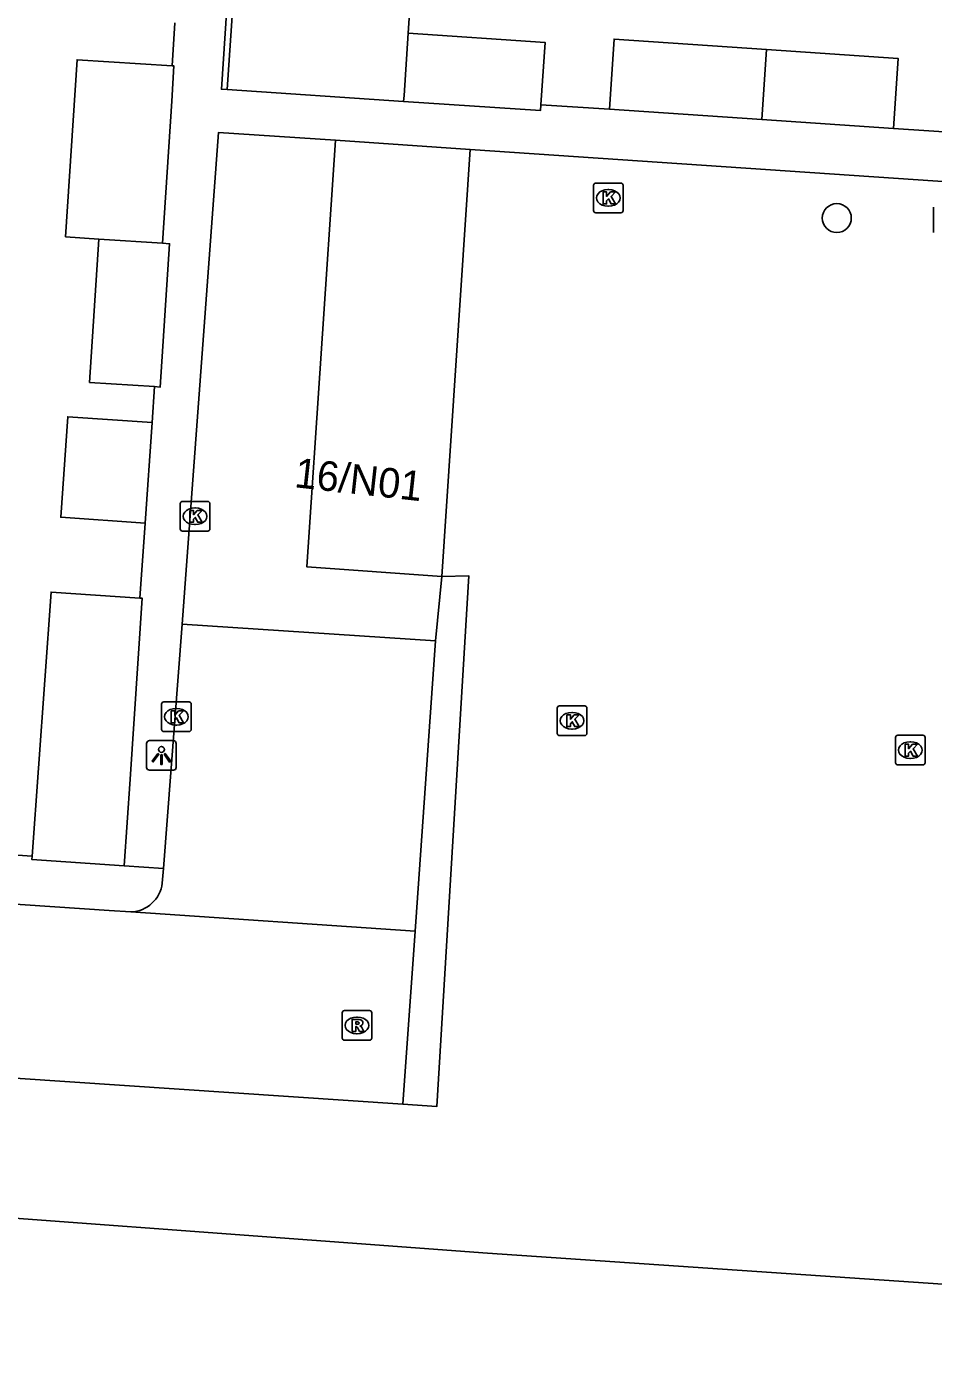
# Model space of a CAD drawing. Extents: x 161848 to 162726, y 385382 to 386521.
# Drawn here: x 162042.65 to 162073.24, y 385672.52 to 385717.48 of the extents above; entities that cross this region are included whole.
import ezdxf

# ---------------------------------------------------------------- set-up
doc = ezdxf.new("R2010")
doc.units = 0
for name, color, linetype in [('IMGEO_Boom', 7, 'Continuous'), ('IMGEO_Hek', 7, 'Continuous'), ('IMGEO_Kolk', 7, 'Continuous'), ('IMGEO_Lichtpunt', 7, 'Continuous'), ('IMGEO_Muur', 7, 'Continuous'), ('IMGEO_Pand', 7, 'Continuous'), ('IMGEO_Pand_nummerreeks', 7, 'Continuous'), ('IMGEO_Rijbaan_lokaal_open', 7, 'Continuous'), ('IMGEO_Rioolput', 7, 'Continuous'), ('IMGEO_Terreindeel_open', 7, 'Continuous'), ('IMGEO_Voetpad_open', 7, 'Continuous')]:
    doc.layers.add(name, color=color, linetype=linetype)

msp = doc.modelspace()

# ---------------------------------------------------------------- linework, layer by layer
at = {"layer": 'IMGEO_Boom'}
msp.add_circle((162069.987, 385711.023), 0.489, dxfattribs=at)
at = {"layer": 'IMGEO_Hek'}
msp.add_lwpolyline([(162056.66, 385698.935), (162057.566, 385698.956), (162056.491, 385681.053)], dxfattribs=at)
at = {"layer": 'IMGEO_Kolk'}
for p, q in [((162061.851, 385712.202), (162062.703, 385712.202)), ((162061.776, 385711.276), (162061.776, 385712.128)), ((162062.264, 385711.982), (162062.289, 385711.982)), ((162062.777, 385712.128), (162062.777, 385711.276)), ((162062.287, 385711.422), (162062.262, 385711.422)), ((162073.244, 385710.539), (162073.244, 385711.391)), ((162062.703, 385711.202), (162061.851, 385711.202)), ((162047.906, 385701.462), (162048.758, 385701.462)), ((162047.831, 385700.536), (162047.831, 385701.388)), ((162048.319, 385701.242), (162048.344, 385701.242)), ((162048.832, 385701.388), (162048.832, 385700.536)), ((162048.342, 385700.682), (162048.317, 385700.682)), ((162048.758, 385700.462), (162047.906, 385700.462)), ((162047.275, 385694.699), (162048.127, 385694.699)), ((162047.2, 385693.773), (162047.2, 385694.625)), ((162047.688, 385694.479), (162047.713, 385694.479)), ((162048.201, 385694.625), (162048.201, 385693.773)), ((162060.552, 385693.639), (162060.552, 385694.491)), ((162060.627, 385694.565), (162061.479, 385694.565)), ((162061.04, 385694.345), (162061.065, 385694.345)), ((162061.553, 385694.491), (162061.553, 385693.639)), ((162047.711, 385693.919), (162047.686, 385693.919)), ((162061.063, 385693.785), (162061.038, 385693.785)), ((162048.127, 385693.699), (162047.275, 385693.699)), ((162061.479, 385693.565), (162060.627, 385693.565)), ((162071.967, 385692.647), (162071.967, 385693.499)), ((162072.042, 385693.573), (162072.894, 385693.573)), ((162072.455, 385693.353), (162072.48, 385693.353)), ((162072.968, 385693.499), (162072.968, 385692.647)), ((162072.894, 385692.573), (162072.042, 385692.573)), ((162072.478, 385692.793), (162072.453, 385692.793))]:
    msp.add_line(p, q, dxfattribs=at)
for points in [[(162061.851, 385712.202), (162062.703, 385712.202)], [(162061.776, 385711.276), (162061.776, 385712.128)], [(162062.097, 385711.902), (162062.22, 385711.902), (162062.22, 385711.751), (162062.35, 385711.902), (162062.514, 385711.902), (162062.368, 385711.751), (162062.521, 385711.502), (162062.369, 385711.502), (162062.284, 385711.666), (162062.22, 385711.599), (162062.22, 385711.502), (162062.097, 385711.502), (162062.097, 385711.902)], [(162062.777, 385712.128), (162062.777, 385711.276)], [(162073.244, 385710.539), (162073.244, 385711.391)], [(162062.703, 385711.202), (162061.851, 385711.202)], [(162047.906, 385701.462), (162048.758, 385701.462)], [(162047.831, 385700.536), (162047.831, 385701.388)], [(162048.152, 385701.162), (162048.275, 385701.162), (162048.275, 385701.011), (162048.405, 385701.162), (162048.569, 385701.162), (162048.423, 385701.011), (162048.576, 385700.762), (162048.424, 385700.762), (162048.339, 385700.926), (162048.275, 385700.859), (162048.275, 385700.762), (162048.152, 385700.762), (162048.152, 385701.162)], [(162048.832, 385701.388), (162048.832, 385700.536)], [(162048.758, 385700.462), (162047.906, 385700.462)], [(162047.275, 385694.699), (162048.127, 385694.699)], [(162047.2, 385693.773), (162047.2, 385694.625)], [(162047.521, 385694.399), (162047.644, 385694.399), (162047.644, 385694.248), (162047.774, 385694.399), (162047.938, 385694.399), (162047.792, 385694.248), (162047.945, 385693.999), (162047.793, 385693.999), (162047.708, 385694.163), (162047.644, 385694.096), (162047.644, 385693.999), (162047.521, 385693.999), (162047.521, 385694.399)], [(162048.201, 385694.625), (162048.201, 385693.773)], [(162060.552, 385693.639), (162060.552, 385694.491)], [(162060.627, 385694.565), (162061.479, 385694.565)], [(162060.873, 385694.265), (162060.996, 385694.265), (162060.996, 385694.114), (162061.126, 385694.265), (162061.29, 385694.265), (162061.144, 385694.114), (162061.297, 385693.865), (162061.145, 385693.865), (162061.06, 385694.029), (162060.996, 385693.962), (162060.996, 385693.865), (162060.873, 385693.865), (162060.873, 385694.265)], [(162061.553, 385694.491), (162061.553, 385693.639)], [(162048.127, 385693.699), (162047.275, 385693.699)], [(162061.479, 385693.565), (162060.627, 385693.565)], [(162071.967, 385692.647), (162071.967, 385693.499)], [(162072.042, 385693.573), (162072.894, 385693.573)], [(162072.968, 385693.499), (162072.968, 385692.647)], [(162072.288, 385693.273), (162072.411, 385693.273), (162072.411, 385693.122), (162072.541, 385693.273), (162072.705, 385693.273), (162072.559, 385693.122), (162072.712, 385692.873), (162072.56, 385692.873), (162072.475, 385693.037), (162072.411, 385692.97), (162072.411, 385692.873), (162072.288, 385692.873), (162072.288, 385693.273)], [(162072.894, 385692.573), (162072.042, 385692.573)]]:
    msp.add_lwpolyline(points, dxfattribs=at)
for centre, start, end in [((162061.853, 385712.126), 91.552, 178.448), ((162061.853, 385712.126), 91.552, 178.448), ((162062.701, 385712.126), 1.552, 88.448), ((162062.701, 385712.126), 1.552, 88.448), ((162061.853, 385711.278), 181.552, 268.448), ((162061.853, 385711.278), 181.552, 268.448), ((162062.701, 385711.278), 271.552, 358.448), ((162062.701, 385711.278), 271.552, 358.448), ((162047.908, 385701.386), 91.552, 178.448), ((162047.908, 385701.386), 91.552, 178.448), ((162048.756, 385701.386), 1.552, 88.448), ((162048.756, 385701.386), 1.552, 88.448), ((162047.908, 385700.538), 181.552, 268.448), ((162047.908, 385700.538), 181.552, 268.448), ((162048.756, 385700.538), 271.552, 358.448), ((162048.756, 385700.538), 271.552, 358.448), ((162047.277, 385694.623), 91.552, 178.448), ((162047.277, 385694.623), 91.552, 178.448), ((162048.125, 385694.623), 1.552, 88.448), ((162048.125, 385694.623), 1.552, 88.448), ((162060.629, 385694.489), 91.552, 178.448), ((162060.629, 385694.489), 91.552, 178.448), ((162061.477, 385694.489), 1.552, 88.448), ((162061.477, 385694.489), 1.552, 88.448), ((162047.277, 385693.775), 181.552, 268.448), ((162047.277, 385693.775), 181.552, 268.448), ((162048.125, 385693.775), 271.552, 358.448), ((162048.125, 385693.775), 271.552, 358.448), ((162060.629, 385693.641), 181.552, 268.448), ((162060.629, 385693.641), 181.552, 268.448), ((162061.477, 385693.641), 271.552, 358.448), ((162061.477, 385693.641), 271.552, 358.448), ((162072.044, 385693.497), 91.552, 178.448), ((162072.044, 385693.497), 91.552, 178.448), ((162072.892, 385693.497), 1.552, 88.448), ((162072.892, 385693.497), 1.552, 88.448), ((162072.044, 385692.649), 181.552, 268.448), ((162072.044, 385692.649), 181.552, 268.448), ((162072.892, 385692.649), 271.552, 358.448), ((162072.892, 385692.649), 271.552, 358.448)]:
    msp.add_arc(centre, 0.0765, start, end, dxfattribs=at)
for centre, major_axis, ratio, start_param, end_param in [((162062.263, 385711.702), (-0.387, 0.002), 0.722429, 4.712389, 7.853982), ((162062.288, 385711.702), (-0.39, 0.002), 0.717154, 1.570796, 4.712389), ((162048.318, 385700.962), (-0.387, 0.002), 0.722429, 4.712389, 7.853982), ((162048.343, 385700.962), (-0.39, 0.002), 0.717154, 1.570796, 4.712389), ((162047.687, 385694.199), (-0.387, 0.002), 0.722429, 4.712389, 7.853982), ((162047.712, 385694.199), (-0.39, 0.002), 0.717154, 1.570796, 4.712389), ((162061.039, 385694.065), (-0.387, 0.002), 0.722429, 4.712389, 7.853982), ((162061.064, 385694.065), (-0.39, 0.002), 0.717154, 1.570796, 4.712389), ((162072.454, 385693.073), (-0.387, 0.002), 0.722429, 4.712389, 7.853982), ((162072.479, 385693.073), (-0.39, 0.002), 0.717154, 1.570796, 4.712389)]:
    msp.add_ellipse(centre, major_axis=major_axis, ratio=ratio, start_param=start_param, end_param=end_param, dxfattribs=at)
at = {"layer": 'IMGEO_Lichtpunt'}
for p, q in [((162046.697, 385693.299), (162046.697, 385692.492)), ((162046.697, 385693.299), (162046.697, 385692.492)), ((162047.599, 385693.394), (162046.791, 385693.394)), ((162047.599, 385693.394), (162046.791, 385693.394)), ((162047.693, 385692.492), (162047.693, 385693.299)), ((162047.693, 385692.492), (162047.693, 385693.299)), ((162046.791, 385692.398), (162047.599, 385692.398)), ((162046.791, 385692.398), (162047.599, 385692.398))]:
    msp.add_line(p, q, dxfattribs=at)
for points in [[(162047.071, 385692.963), (162047.11, 385692.935), (162046.922, 385692.673), (162046.884, 385692.7), (162047.071, 385692.963)], [(162047.173, 385692.915), (162047.22, 385692.915), (162047.22, 385692.593), (162047.173, 385692.593), (162047.173, 385692.915)], [(162047.283, 385692.935), (162047.321, 385692.962), (162047.508, 385692.7), (162047.469, 385692.672), (162047.283, 385692.935)]]:
    msp.add_lwpolyline(points, dxfattribs=at)
msp.add_circle((162047.196, 385693.097), 0.0994, dxfattribs=at)
for centre, start, end in [((162046.791, 385693.299), 90, 180), ((162046.791, 385693.299), 90, 180), ((162047.599, 385693.299), 0, 90), ((162047.599, 385693.299), 0, 90), ((162046.791, 385692.492), 180, 270), ((162046.791, 385692.492), 180, 270), ((162047.599, 385692.492), 270, 0), ((162047.599, 385692.492), 270, 360)]:
    msp.add_arc(centre, 0.0946, start, end, dxfattribs=at)
at = {"layer": 'IMGEO_Muur'}
msp.add_lwpolyline([(162056.491, 385681.053), (162055.347, 385681.13), (162038.387, 385682.266), (162034.495, 385682.526)], dxfattribs=at)
at = {"layer": 'IMGEO_Pand'}
for points in [[(162055.524, 385717.259), (162055.659, 385719.271), (162049.703, 385719.67), (162049.415, 385715.357)], [(162055.524, 385717.259), (162055.383, 385715.157), (162055.37, 385714.959)], [(162059.999, 385714.847), (162060.14, 385716.95), (162055.524, 385717.259)], [(162062.312, 385714.692), (162062.473, 385717.058), (162067.61, 385716.71)], [(162067.61, 385716.71), (162067.454, 385714.344)], [(162067.61, 385716.71), (162072.057, 385716.408), (162071.896, 385714.042)], [(162045.086, 385710.314), (162043.96, 385710.389), (162044.347, 385716.364), (162047.558, 385716.156)], [(162047.558, 385716.156), (162047.619, 385716.152), (162047.542, 385714.966), (162047.232, 385710.172)], [(162055.37, 385714.959), (162049.415, 385715.357)], [(162055.37, 385714.959), (162059.986, 385714.65), (162059.999, 385714.847)], [(162067.454, 385714.344), (162062.312, 385714.692)], [(162071.896, 385714.042), (162067.454, 385714.344)], [(162053.075, 385713.645), (162052.107, 385699.252), (162056.66, 385698.935)], [(162053.075, 385713.645), (162057.615, 385713.34)], [(162057.615, 385713.34), (162056.66, 385698.935)], [(162046.958, 385705.335), (162044.772, 385705.477), (162045.086, 385710.314)], [(162045.086, 385710.314), (162047.232, 385710.172)], [(162047.232, 385710.172), (162047.47, 385710.156), (162047.156, 385705.322), (162046.958, 385705.335)], [(162046.644, 385700.731), (162043.801, 385700.928), (162044.036, 385704.32), (162046.879, 385704.122)], [(162046.879, 385704.122), (162046.644, 385700.731)], [(162042.835, 385689.5), (162043.472, 385698.403), (162046.468, 385698.203)], [(162046.468, 385698.203), (162046.549, 385698.198), (162046.137, 385692.097), (162045.94, 385689.173)], [(162042.835, 385689.5), (162042.827, 385689.383), (162045.94, 385689.173)], [(162110.912, 385672.522), (162058.2, 385676.103), (162034.17, 385677.885)]]:
    msp.add_lwpolyline(points, dxfattribs=at)
at = {"layer": 'IMGEO_Rijbaan_lokaal_open'}
for points in [[(162047.901, 385697.328), (162049.124, 385713.91), (162053.075, 385713.645)], [(162056.66, 385698.935), (162056.443, 385696.757)], [(162047.901, 385697.328), (162047.264, 385689.084)], [(162056.443, 385696.757), (162047.901, 385697.328)], [(162055.757, 385686.967), (162056.443, 385696.757)], [(162047.264, 385689.084), (162047.224, 385688.589)], [(162055.757, 385686.967), (162046.169, 385687.615)]]:
    msp.add_lwpolyline(points, dxfattribs=at)
msp.add_arc((162046.122, 385688.725), 1.111, 272.4504, 352.9774, dxfattribs=at)
at = {"layer": 'IMGEO_Rioolput'}
for p, q in [((162053.294, 385683.361), (162053.294, 385684.213)), ((162053.369, 385684.287), (162054.221, 385684.287)), ((162053.782, 385684.067), (162053.807, 385684.067)), ((162054.295, 385684.213), (162054.295, 385683.361)), ((162053.805, 385683.507), (162053.78, 385683.507)), ((162054.221, 385683.287), (162053.369, 385683.287))]:
    msp.add_line(p, q, dxfattribs=at)
for points in [[(162053.294, 385683.361), (162053.294, 385684.213)], [(162053.369, 385684.287), (162054.221, 385684.287)], [(162053.883, 385683.985), (162053.631, 385683.987), (162053.631, 385683.587)], [(162053.809, 385683.906), (162053.755, 385683.906), (162053.755, 385683.825)], [(162054.295, 385684.213), (162054.295, 385683.361)], [(162053.631, 385683.587), (162053.755, 385683.587), (162053.755, 385683.749), (162053.766, 385683.749)], [(162053.755, 385683.825), (162053.807, 385683.825)], [(162053.813, 385683.72), (162053.884, 385683.587), (162054.024, 385683.587), (162053.959, 385683.713)], [(162054.221, 385683.287), (162053.369, 385683.287)]]:
    msp.add_lwpolyline(points, dxfattribs=at)
for centre, radius, start, end in [((162053.371, 385684.211), 0.0765, 91.552, 178.448), ((162053.371, 385684.211), 0.0765, 91.552, 178.448), ((162053.815, 385683.81), 0.0964, 77.0061, 93.1865), ((162053.829, 385683.867), 0.0378, 276.6634, 79.6772), ((162053.882, 385683.875), 0.109, 350.3612, 89.416), ((162053.88, 385683.875), 0.112, 277.5842, 350.9817), ((162054.219, 385684.211), 0.0765, 1.552, 88.448), ((162054.219, 385684.211), 0.0765, 1.552, 88.448), ((162053.765, 385683.696), 0.0533, 26.0293, 88.6989), ((162053.791, 385684.014), 0.19, 274.7715, 282.9687), ((162053.864, 385683.66), 0.108, 29.5134, 73.7905), ((162053.371, 385683.363), 0.0765, 181.552, 268.448), ((162053.371, 385683.363), 0.0765, 181.552, 268.448), ((162054.219, 385683.363), 0.0765, 271.552, 358.448), ((162054.219, 385683.363), 0.0765, 271.552, 358.448)]:
    msp.add_arc(centre, radius, start, end, dxfattribs=at)
for centre, major_axis, ratio, start_param, end_param in [((162053.781, 385683.787), (-0.387, 0.002), 0.722429, 4.712389, 7.853982), ((162053.806, 385683.787), (-0.39, 0.002), 0.717154, 1.570796, 4.712389)]:
    msp.add_ellipse(centre, major_axis=major_axis, ratio=ratio, start_param=start_param, end_param=end_param, dxfattribs=at)
at = {"layer": 'IMGEO_Terreindeel_open'}
msp.add_lwpolyline([(162056.66, 385698.935), (162057.566, 385698.956), (162056.491, 385681.053), (162055.347, 385681.13)], dxfattribs=at)
at = {"layer": 'IMGEO_Voetpad_open'}
for points in [[(162049.415, 385715.357), (162049.22, 385715.37), (162049.962, 385726.657)], [(162047.558, 385716.156), (162047.653, 385717.611)], [(162062.312, 385714.692), (162059.999, 385714.847)], [(162074.284, 385713.89), (162071.896, 385714.042)], [(162117.085, 385709.313), (162057.615, 385713.34)], [(162046.879, 385704.122), (162046.958, 385705.335)], [(162046.468, 385698.203), (162046.644, 385700.731)], [(162026.232, 385690.631), (162027.726, 385690.519), (162027.721, 385690.258), (162036.352, 385689.938), (162042.835, 385689.5)], [(162046.169, 385687.615), (162045.435, 385687.665), (162031.577, 385688.596), (162027.604, 385688.858)], [(162045.94, 385689.173), (162047.264, 385689.084)], [(162055.347, 385681.13), (162055.757, 385686.967)], [(162055.347, 385681.13), (162038.387, 385682.266), (162038.412, 385682.641), (162036.684, 385682.769), (162034.52, 385682.885), (162034.495, 385682.526), (162034.17, 385677.885)]]:
    msp.add_lwpolyline(points, dxfattribs=at)

# ---------------------------------------------------------------- texts
at = {"layer": 'IMGEO_Pand_nummerreeks'}
msp.add_text('16/N01', height=1, rotation=353.6598, dxfattribs=at).set_placement((162051.656, 385701.946))

doc.saveas('drawing.dxf')
